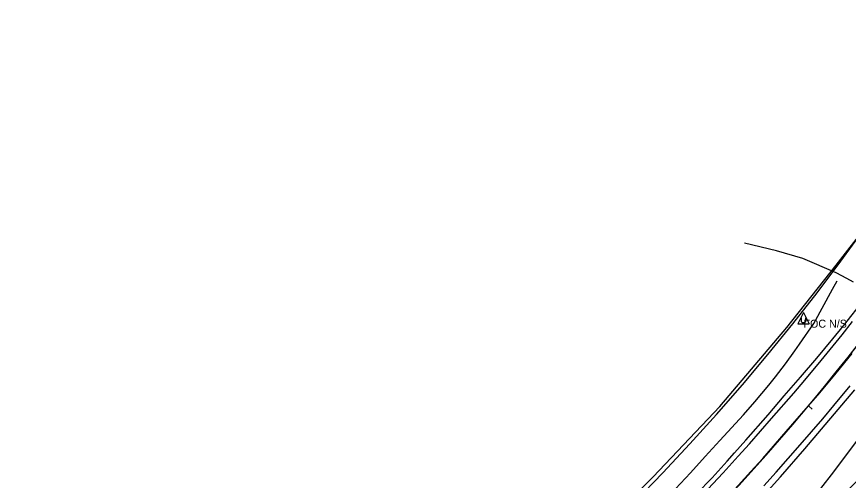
# Model space of a CAD drawing. Extents: x 1674300 to 1677920, y 225056 to 231852.
# Drawn here: x 1676544 to 1677064, y 228011 to 228301 of the extents above; entities that cross this region are included whole.
import ezdxf

# ---------------------------------------------------------------- set-up
doc = ezdxf.new("R2010")
doc.units = 0
for name, color, linetype in [('R_Horz Alg', 7, 'Continuous'), ('R_Horz Alg Annot', 7, 'Continuous'), ('R_Proposed Const Limits_Fill', 7, 'Continuous'), ('R_Proposed Road_Lane', 7, 'Continuous'), ('R_Proposed Road_Shoulder', 7, 'Continuous'), ('S_DITCHLINE', 7, 'Continuous'), ('S_EDGE_PAVEMENT', 7, 'Continuous'), ('S_EXIST_ROW', 7, 'Continuous'), ('S_EXISTING_ALIGNMENT', 7, 'Continuous'), ('S_FIBER_OPTIC_CABLE', 7, 'Continuous'), ('S_PAVEMENT_CROWN', 7, 'Continuous'), ('S_SHOULDER', 7, 'Continuous'), ('S_UNDERGROUND_CABLE', 7, 'Continuous'), ('S_UTILITY_POLE_ANNOT', 7, 'Continuous'), ('S_UTL_PT_SYM', 7, 'Continuous')]:
    doc.layers.add(name, color=color, linetype=linetype)

msp = doc.modelspace()

# ---------------------------------------------------------------- linework, layer by layer
at = {"layer": 'R_Horz Alg'}
for centre, radius, end in [((1675928.16, 228988.54), 1449, 0.80558), ((1676402.48, 228665.51), 954.93, 328.88259)]:
    msp.add_arc(centre, radius, 296.0624, end, dxfattribs=at)
at = {"layer": 'R_Horz Alg Annot'}
msp.add_lwpolyline([(1677040.98, 228055.84), (1677038.68, 228057.77)], dxfattribs=at)
at = {"layer": 'R_Proposed Const Limits_Fill'}
msp.add_arc((1676364.65, 228668.23), 963.36, 309.06481, 319.55161, dxfattribs=at)
at = {"layer": 'R_Proposed Road_Lane'}
msp.add_arc((1676402.48, 228665.51), 947.43, 296.0624, 317.63818, dxfattribs=at)
at = {"layer": 'R_Proposed Road_Shoulder'}
msp.add_arc((1676402.48, 228665.51), 941.43, 296.0624, 317.05629, dxfattribs=at)
at = {"layer": 'S_DITCHLINE'}
for points in [[(1677066.9, 228135.11), (1677062.68, 228137.31), (1677055.92, 228140.95), (1677035.17, 228149.97), (1677018.6, 228154.56), (1676998.71, 228159.55)], [(1676955.51, 228005.96), (1676964.85, 228016), (1676974.11, 228026.12), (1676983.36, 228036.25), (1676997.99, 228052.3), (1677005.17, 228060.44), (1677013.85, 228070.76), (1677018.06, 228076.02), (1677024.23, 228084.04), (1677030.2, 228092.21), (1677033.11, 228096.36), (1677042.01, 228109.26), (1677053.62, 228130.79), (1677056.62, 228135.95)], [(1677046.49, 228006.3), (1677054.51, 228016.66), (1677069.4, 228036.4)]]:
    msp.add_lwpolyline(points, dxfattribs=at)
at = {"layer": 'S_EDGE_PAVEMENT'}
for points in [[(1676975.83, 228005.73), (1676985.29, 228016.04), (1676994.74, 228026.34), (1677001.75, 228034.14), (1677015.66, 228049.85), (1677029.54, 228065.85), (1677036.41, 228073.91), (1677046.61, 228086.1), (1677059.75, 228102.25), (1677066.21, 228110.42)], [(1677010.8, 228007.79), (1677018.43, 228016.32), (1677033.54, 228033.53), (1677047.55, 228049.79), (1677054.49, 228057.98), (1677064.77, 228070.36)]]:
    msp.add_lwpolyline(points, dxfattribs=at)
at = {"layer": 'S_EXIST_ROW'}
msp.add_arc((1675926.71, 228989.39), 1410.53, 295.94359, 0.85682, dxfattribs=at)
at = {"layer": 'S_EXISTING_ALIGNMENT'}
msp.add_arc((1675926.71, 228989.39), 1450.53, 315.98862, 345.81316, dxfattribs=at)
at = {"layer": 'S_FIBER_OPTIC_CABLE'}
for p, q in [((1677055.89, 228145.71), (1677094.67, 228195.4)), ((1677025.14, 228106.74), (1677055.89, 228145.71)), ((1676983.24, 228057.34), (1677025.14, 228106.74)), ((1676941.57, 228013.45), (1676983.24, 228057.34)), ((1676902.41, 227973.8), (1676941.57, 228013.45))]:
    msp.add_line(p, q, dxfattribs=at)
at = {"layer": 'S_PAVEMENT_CROWN'}
msp.add_lwpolyline([(1676988.75, 228001.5), (1677002.67, 228016.75), (1677010.08, 228025.04), (1677024.77, 228041.73), (1677038.77, 228057.88), (1677045.7, 228066.01), (1677055.98, 228078.31), (1677065.91, 228090.56)], dxfattribs=at)
at = {"layer": 'S_SHOULDER'}
for points in [[(1676968.79, 228002.8), (1676978.38, 228012.96), (1676987.84, 228023.23), (1676992.51, 228028.41), (1676999.51, 228036.33), (1677013.38, 228052.28), (1677023.58, 228064.01), (1677033.77, 228075.74), (1677043.85, 228087.56), (1677053.94, 228099.73), (1677060.59, 228107.91), (1677073.75, 228124.38)], [(1677013.47, 228004.94), (1677021.15, 228013.58), (1677036.33, 228031), (1677046.83, 228043.27), (1677057.33, 228055.54), (1677067.66, 228067.94)]]:
    msp.add_lwpolyline(points, dxfattribs=at)
at = {"layer": 'S_UNDERGROUND_CABLE'}
for p, q in [((1677035.55, 228116.19), (1677032.02, 228109.1)), ((1677035.55, 228116.19), (1677039.04, 228109.1)), ((1677032.02, 228109.1), (1677039.04, 228109.1)), ((1677034.35, 228110.34), (1677034.35, 228112.78)), ((1677034.97, 228109.68), (1677034.35, 228110.34)), ((1677036.17, 228109.68), (1677034.97, 228109.68)), ((1677036.71, 228110.34), (1677036.17, 228109.68)), ((1677036.71, 228112.78), (1677036.71, 228110.34))]:
    msp.add_line(p, q, dxfattribs=at)
at = {"layer": 'S_UTL_PT_SYM'}
for points in [[(1677055.89, 228145.71), (1677055.89, 228145.76), (1677055.89, 228145.71), (1677055.84, 228145.71), (1677055.89, 228145.71), (1677055.89, 228145.66), (1677055.89, 228145.71), (1677055.94, 228145.71)], [(1677025.14, 228106.74), (1677025.14, 228106.79), (1677025.14, 228106.74), (1677025.09, 228106.74), (1677025.14, 228106.74), (1677025.14, 228106.69), (1677025.14, 228106.74), (1677025.19, 228106.74)], [(1676983.24, 228057.34), (1676983.24, 228057.39), (1676983.24, 228057.34), (1676983.19, 228057.34), (1676983.24, 228057.34), (1676983.24, 228057.29), (1676983.24, 228057.34), (1676983.29, 228057.34)], [(1676941.57, 228013.45), (1676941.57, 228013.5), (1676941.57, 228013.45), (1676941.52, 228013.45), (1676941.57, 228013.45), (1676941.57, 228013.4), (1676941.57, 228013.45), (1676941.62, 228013.45)]]:
    msp.add_lwpolyline(points, dxfattribs=at)

# ---------------------------------------------------------------- texts
at = {"layer": 'S_UTILITY_POLE_ANNOT'}
msp.add_text('FOC N/S', height=5, rotation=360, dxfattribs=at).set_placement((1677035.55, 228106.65))

doc.saveas('drawing.dxf')
